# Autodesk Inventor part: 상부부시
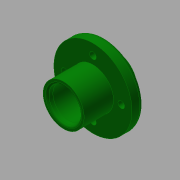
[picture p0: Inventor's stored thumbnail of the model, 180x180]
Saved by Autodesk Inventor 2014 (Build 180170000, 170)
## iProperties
Created: 2015-12
Part Number: 상부부시
Material: 강철, 연강
Document SubType Name: Modeling
Designer: mduedu
Density: 7.86 g/cm^3
Appearance: Dark Green
Author: mduedu
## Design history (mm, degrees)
sketch "스케치1"
  geometry: C1 r 10.5 at (0, 0); C2 r 8 at (0, 0); 1 further point
  constraints: 2 centre point, 2 coincident
  dimensions: "d1" = 21 diameter of C1; "d3" = 16 diameter of C2
extrude "돌출1" new body sketch "스케치1" distance "d4" = 12; taper "d6" = 0 deg; dims "d5" = 15, "d7" = 0
sketch "스케치2"
  geometry: C1 r 20 at (0, 0); C2 r 10.5 at (0, 0) reference; 1 further point
  constraints: 1 centre point, 1 coincident
  dimensions: "d8" = 40 diameter of C1
extrude "돌출2" join sketch "스케치2" distance "d10" = 6; taper "d11" = 0 deg
chamfer "모따기1" distance "d12" = 2.5; stored, may be unused: second distance "d13" = 2, angle "d14" = 10 deg
chamfer "모따기2" distance "d15" = 2.5; stored, may be unused: second distance "d16" = 2, angle "d17" = 10 deg
fillet "모깎기1" dims "d18" = 1
fillet "모깎기2" dims "d19" = 2
sketch "스케치3" dims "d20" = 29
  geometry: 6 further points
  constraints: 2 vertical alignment, 1 coincident, 7 other
  dimensions: "d24" = 360 deg dimension on point (0, 0) point (0, 14.5) (derived)
sketch "스케치4"
  geometry: 4 further points
hole "구멍1" sketch "스케치4" at (-14.5, 0), (0, -14.5), (14.5, 0), (0, 14.5) diameter "d26" = 3.4; stored, may be unused: countersink angle "d30" = 90 deg, drill point angle "d32" = 0 deg; dims "d27" = 6, "d28" = 6.5, "d29" = 3.4, "d31" = 8
fillet "모깎기3" dims "d33" = 1
node "솔리드1"
